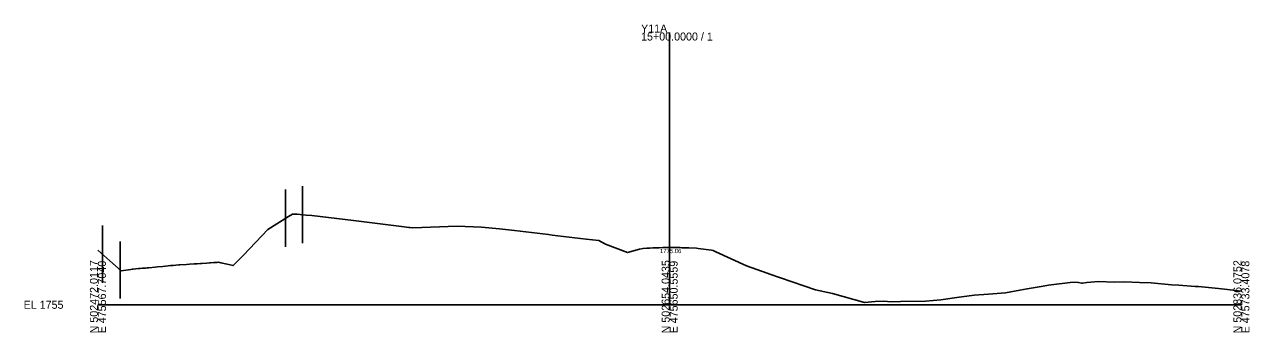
# Model space of a CAD drawing. Extents: x -26 to 403, y -10 to 5098.
# Drawn here: x -25.7 to 402.8, y 4990.3 to 5098 of the extents above; entities that cross this region are included whole.
import ezdxf

# ---------------------------------------------------------------- set-up
doc = ezdxf.new("R2010")
doc.units = 0
for name, color, linetype in [('Exist Cross Section Cell', 7, 'Continuous'), ('Exist XS Center Line Elevation Label', 7, 'Continuous'), ('Exist XS Ground Line', 7, 'Continuous'), ('Scratch_Level_5', 7, 'Continuous')]:
    doc.layers.add(name, color=color, linetype=linetype)

msp = doc.modelspace()

# ---------------------------------------------------------------- linework, layer by layer
at = {"layer": 'Exist Cross Section Cell'}
for p, q in [((200, 5000), (200, 5095.23)), ((0, 5000), (200, 5000)), ((200, 5000), (400, 5000))]:
    msp.add_line(p, q, dxfattribs=at)
at = {"layer": 'Exist XS Ground Line'}
msp.add_lwpolyline([(0, 5019.14), (4.21, 5015.35), (8.18, 5011.82), (11.56, 5012.35), (12.02, 5012.42), (12.37, 5012.46), (14.23, 5012.65), (14.77, 5012.7), (15.54, 5012.77), (16.6, 5012.86), (17.21, 5012.92), (17.75, 5012.97), (20.03, 5013.18), (20.81, 5013.25), (22.7, 5013.43), (24.56, 5013.61), (25.38, 5013.69), (26.29, 5013.77), (27.25, 5013.86), (28.24, 5013.92), (28.66, 5013.95), (30.99, 5014.11), (32.08, 5014.18), (33.69, 5014.28), (33.99, 5014.3), (34.68, 5014.35), (35.86, 5014.42), (36.34, 5014.45), (38.05, 5014.57), (39.05, 5014.64), (39.35, 5014.66), (40.59, 5014.74), (41.74, 5014.82), (42.2, 5014.85), (42.96, 5014.68), (45.23, 5014.15), (47.28, 5013.69), (50.93, 5017.33), (59.46, 5026.29), (66.61, 5030.89), (68.01, 5031.74), (69.73, 5031.64), (72.86, 5031.4), (74.8, 5031.2), (89.41, 5029.44), (107.07, 5027.24), (108.78, 5027.03), (109.12, 5026.98), (110.15, 5026.93), (125.72, 5027.44), (134.13, 5027.13), (140.43, 5026.53), (145.72, 5026.01), (157.64, 5024.57), (158.89, 5024.37), (170.79, 5023), (175.22, 5022.47), (177.52, 5021.19), (185.25, 5018.28), (189.42, 5019.4), (190.73, 5019.74), (192.01, 5019.79), (193.01, 5019.83), (194.16, 5019.87), (195.76, 5019.93), (196.35, 5019.95), (197.63, 5019.99), (198.51, 5020.02), (200.12, 5020.07), (201.23, 5020.06), (203.66, 5019.99), (204.22, 5019.97), (206.72, 5019.87), (209.35, 5019.75), (209.96, 5019.73), (214.63, 5019.07), (215.17, 5018.98), (216.2, 5018.5), (226.85, 5013.62), (234.06, 5011.09), (234.41, 5010.97), (234.75, 5010.86), (250.98, 5005.24), (256.97, 5003.9), (268.11, 5000.77), (271.91, 5001.16), (274.73, 5001.26), (277.73, 5001.08), (280.79, 5001.14), (289.54, 5001.28), (294.82, 5001.76), (300.5, 5002.55), (306.49, 5003.33), (309.93, 5003.55), (311.49, 5003.74), (317.48, 5004.15), (322.48, 5005.07), (325.03, 5005.58), (330.64, 5006.48), (332.58, 5006.83), (333.47, 5006.95), (340.13, 5007.82), (341.52, 5007.91), (342.95, 5007.8), (344.13, 5007.52), (344.45, 5007.53), (345.93, 5007.74), (349.96, 5008.1), (355.49, 5007.91), (359.1, 5008.05), (364.37, 5007.8), (368.43, 5007.62), (375.56, 5006.98), (378.17, 5006.85), (383.85, 5006.42), (385, 5006.36), (392.05, 5005.7), (395.14, 5005.38), (398.82, 5004.9), (400, 5004.81)], dxfattribs=at)
at = {"layer": 'Scratch_Level_5'}
for p, q in [((65.65, 5040.27), (65.65, 5020.27)), ((71.58, 5041.5), (71.58, 5021.5)), ((1.62, 5027.69), (1.62, 5007.69)), ((7.78, 5022.19), (7.78, 5002.19))]:
    msp.add_line(p, q, dxfattribs=at)

# ---------------------------------------------------------------- texts
at = {"layer": 'Exist Cross Section Cell'}
for s, p in [('Y11A', (190, 5095.23)), ('15+00.0000 / 1', (190, 5092.43)), ('EL 1755', (-26, 4998.6))]:
    msp.add_text(s, height=2.8, dxfattribs=at).set_placement(p)
for s, p in [('N 502472.0117', (0, 4990)), ('E 475567.7040', (2.8, 4990)), ('N 502654.0435', (200, 4990)), ('E 475650.5559', (202.8, 4990)), ('N 502836.0752', (400, 4990)), ('E 475733.4078', (402.8, 4990))]:
    msp.add_text(s, height=2.8, rotation=90, dxfattribs=at).set_placement(p)
at = {"layer": 'Exist XS Center Line Elevation Label'}
msp.add_text('1775.06', height=1.5, dxfattribs=at).set_placement((196.59, 5018.06))

doc.saveas('drawing.dxf')
